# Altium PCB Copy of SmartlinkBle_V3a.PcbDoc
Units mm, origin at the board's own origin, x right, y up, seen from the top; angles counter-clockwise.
Board outline 125 x 27 mm, 6 copper layers (Top Layer, PWR, VCC, GND, Signal, Bottom Layer), stack 1.475 mm thick; 29 components, 147 nets, 142 pads, 70 vias.
Unrouted connection lines stored in the file: 5.
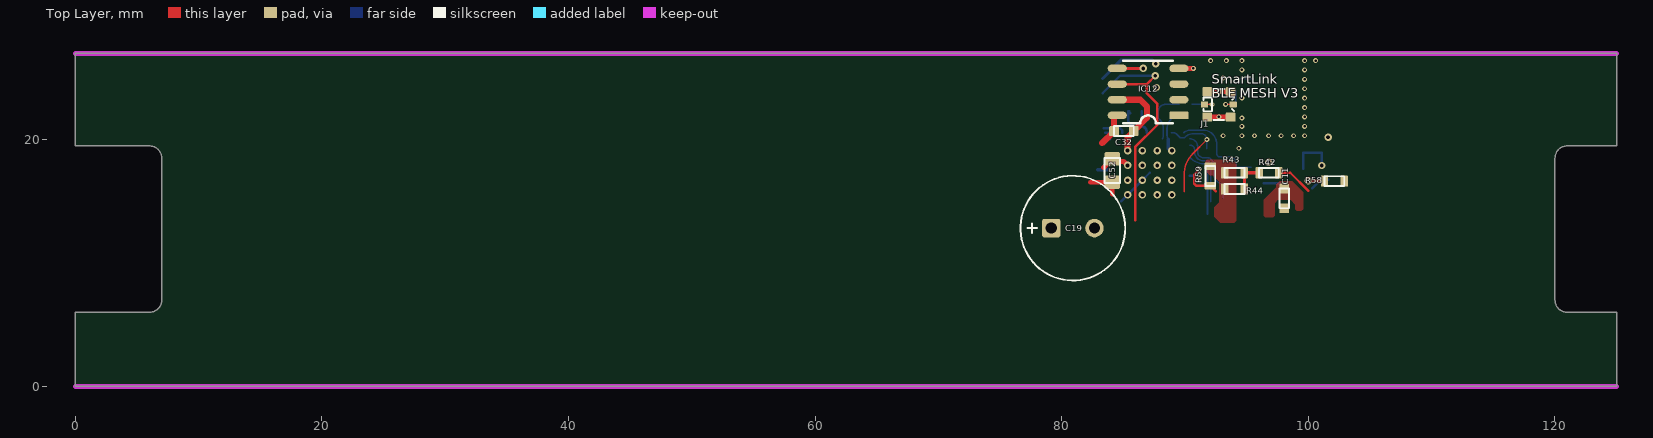
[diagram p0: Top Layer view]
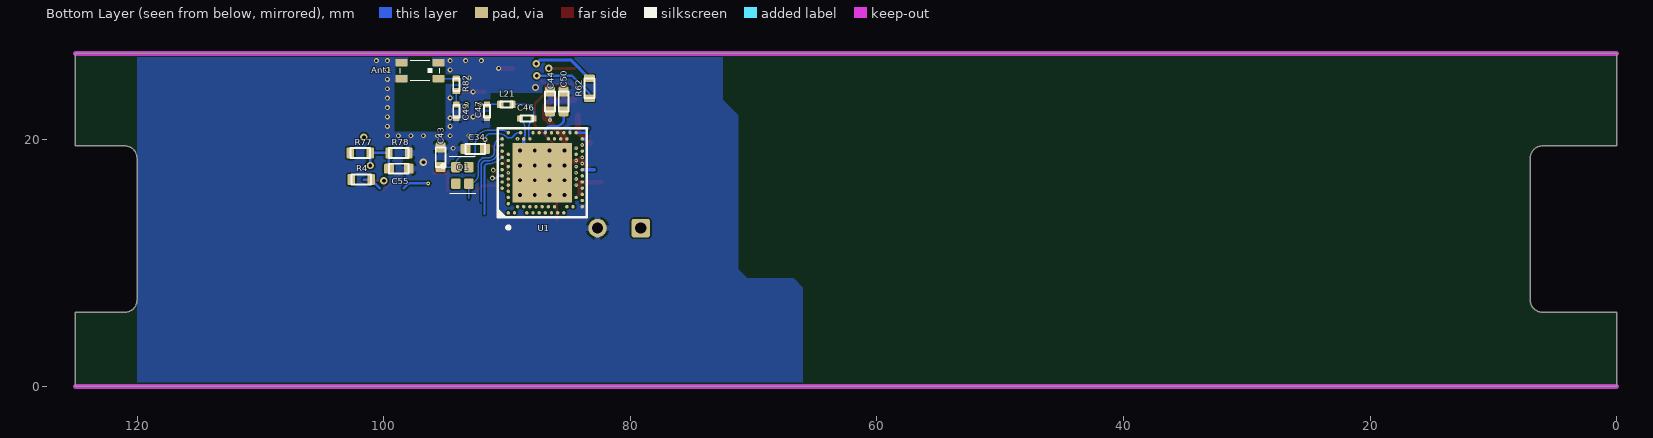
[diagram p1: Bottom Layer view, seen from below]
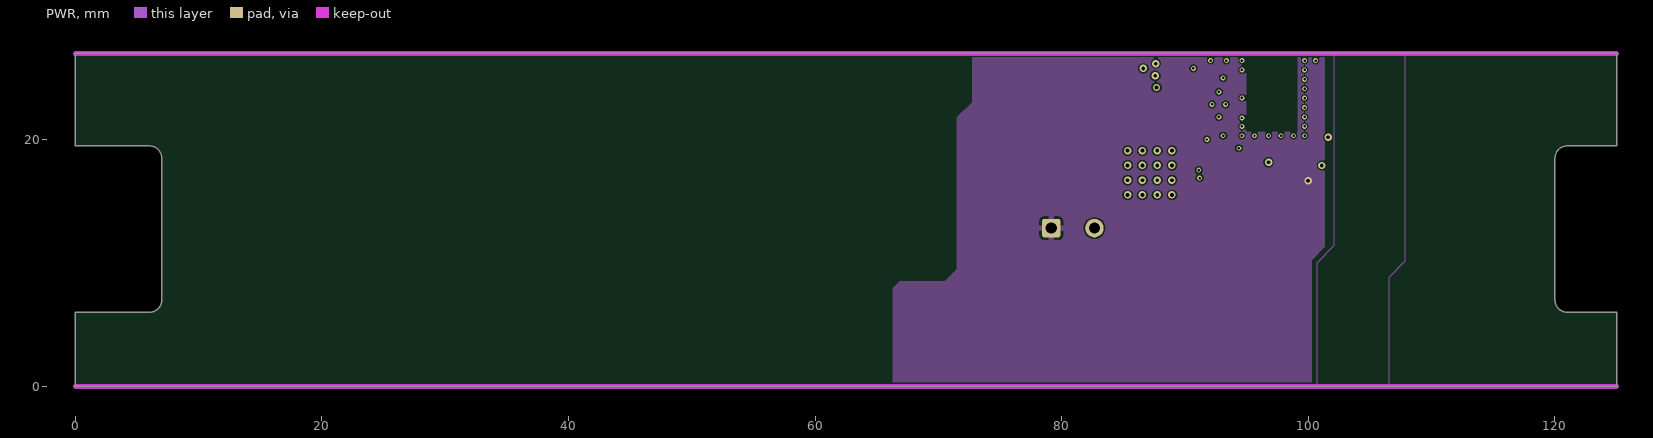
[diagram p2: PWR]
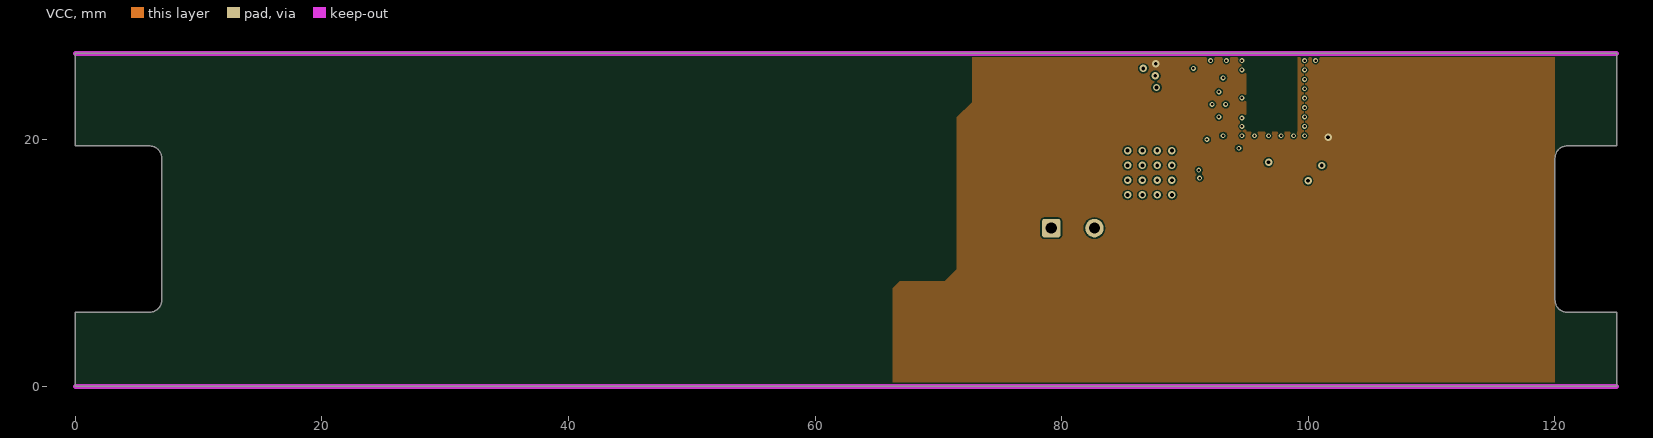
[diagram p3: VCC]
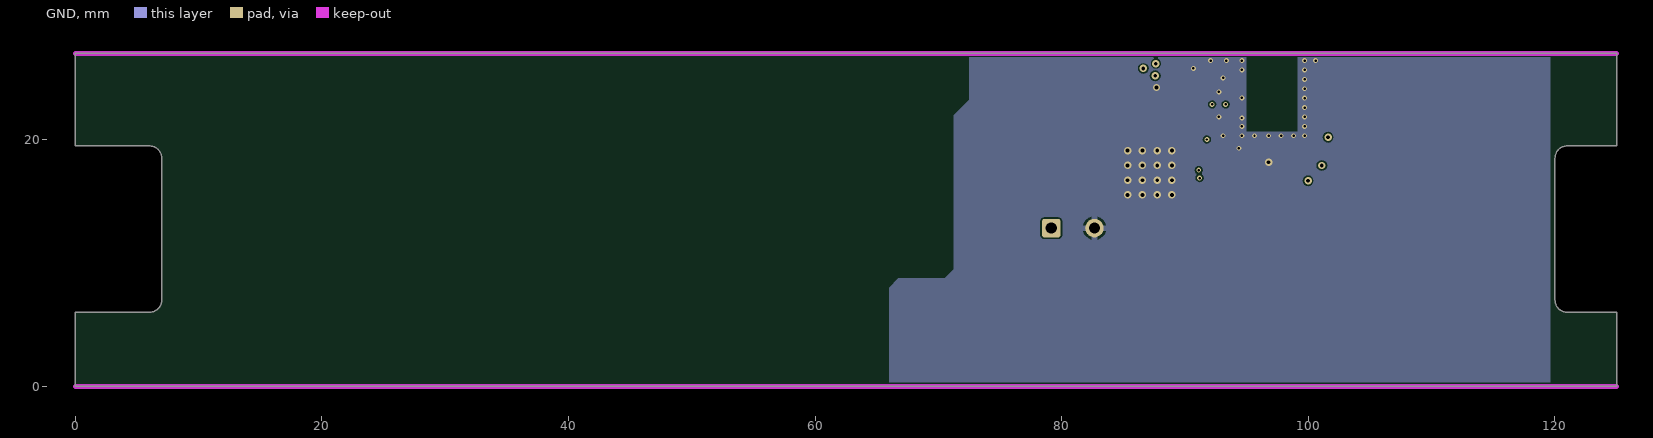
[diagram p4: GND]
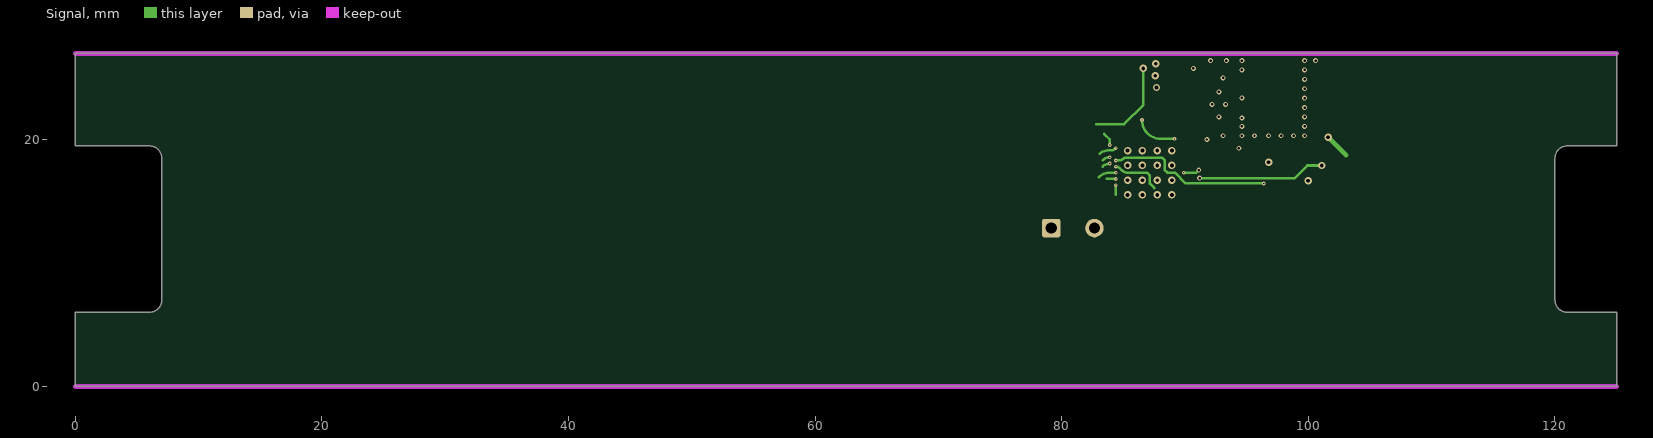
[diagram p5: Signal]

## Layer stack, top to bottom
Top Solder: solder mask 0.015, WE-SM-0001, Dk 3.5
Top Layer: signal copper 0.03
Dielectric 1: prepreg 0.065, WE-PP-0034, Dk 3.5
PWR: signal copper 0.035
Core 1: core 0.51, WE-CO-0050, Dk 5.1
VCC: signal copper 0.035
Dielectric 2: prepreg 0.125, WE-PP-0035, Dk 3.7
GND: signal copper 0.035
Core 2: core 0.51, WE-CO-0050, Dk 5.1
Signal: signal copper 0.035
Dielectric 3: prepreg 0.065, WE-PP-0034, Dk 3.5
Bottom Layer: signal copper 0.03
Bottom Solder: solder mask 0.015, WE-SM-0001, Dk 3.5

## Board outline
0,6 6,6 ccw(c6,7) 7,7 7,18.5 ccw(c6,18.5) 6,19.5 0,19.5 0,27 125,27 125,19.5 121,19.5 ccw(c121,18.5) 120,18.5 120,7 ccw(c121,7) 121,6 125,6 125,0 0,0

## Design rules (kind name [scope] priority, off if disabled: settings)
Clearance "Prim - Sec" [InNetClass('Sec LS') vs (InNetClass('AC N') OR InNetClass('AC Ph') OR InNetClass('Pri HS') OR InNetClass('Pri LS') OR InNetClass('Pri MS') OR InNetClass('Pri SW') OR InNetClass('GND-PRI'))] p1: gap=6 ignorepadtopadclearanceinfootprint=FALSE
Clearance "Bus - N" [InNet('BUS+') vs InNetClass('AC N')or InNetClass('Touch')] p2: gap=2.5 ignorepadtopadclearanceinfootprint=FALSE
Clearance Earth [InNetClass('Earth') vs (InNetClass('AC N') OR InNetClass('AC Ph') OR InNetClass('Pri HS') OR InNetClass('Pri LS') OR InNetClass('Pri MS') OR InNetClass('Pri SW') OR InNetClass('GND-PRI'))] p3: gap=2.5 ignorepadtopadclearanceinfootprint=FALSE
Clearance "AC-PH - AC-N" [InNetClass('AC Ph') vs InNetClass('AC N')] p4: gap=2.5 ignorepadtopadclearanceinfootprint=FALSE
Clearance "Touch - Netz" [InNetClass('Touch') vs (InNetClass('AC N') OR InNetClass('AC Ph') OR InNetClass('Pri HS') OR InNetClass('Pri LS') OR InNetClass('Pri MS') OR InNetClass('Pri SW') OR InNetClass('GND-PRI'))] p5: gap=1 ignorepadtopadclearanceinfootprint=FALSE
Clearance "TouchLS - Netz" [InNetClass('Touch_LS') vs (InNetClass('AC N') OR InNetClass('AC Ph') OR InNetClass('Pri HS') OR InNetClass('Pri LS') OR InNetClass('Pri MS') OR InNetClass('Pri SW') OR InNetClass('GND-PRI'))] p6: gap=0.5 ignorepadtopadclearanceinfootprint=FALSE
Clearance "Bus + to Bus -" [InNet('BUS+') vs InNet('BUS-')] p7: gap=1 ignorepadtopadclearanceinfootprint=FALSE
Clearance "earth Sec" [InNetClass('Earth') vs InNetClass('Sec LS')] p8: gap=1 ignorepadtopadclearanceinfootprint=FALSE
Clearance "AC to Pri" [(InNetClass('AC N') OR InNetClass('AC Ph')) vs (InNetClass('Pri HS') OR InNetClass('Pri LS') OR InNetClass('GND-PRI'))] p9: gap=1 ignorepadtopadclearanceinfootprint=FALSE
Clearance GND-PRI [InNetClass('GND-PRI') vs (InNetClass('AC N') OR InNetClass('AC Ph') OR InNetClass('Pri HS') OR InNetClass('Pri LS') OR InNetClass('Pri MS') OR InNetClass('Pri SW'))] p10: gap=0.99 ignorepadtopadclearanceinfootprint=FALSE
Clearance "Pri SW" [InNetClass('Pri SW')] p11: gap=1 ignorepadtopadclearanceinfootprint=FALSE
Clearance "Pri HS - Pri LS" [InNetClass('Pri HS') vs InNetClass('Pri LS')] p12: gap=1 ignorepadtopadclearanceinfootprint=FALSE
Clearance Pri-MS [InNetClass('Pri MS')] p13: gap=0.5 ignorepadtopadclearanceinfootprint=FALSE
Clearance All [All] p14: gap=0.12 ignorepadtopadclearanceinfootprint=FALSE
ComponentClearance ComponentClearance_C13 [InComponent('C13')] p1: gap=0 collisioncheckmode=3 verticalgap=0 showdistances=TRUE
ComponentClearance ComponentClearance_RTC [InComponent('RTC1')] p2: gap=0 collisioncheckmode=3 verticalgap=0 showdistances=TRUE
ComponentClearance ComponentClearance_Ref [HasFootprint('SMD-REF1')] p3: gap=0 collisioncheckmode=3 verticalgap=0 showdistances=TRUE
ComponentClearance ComponentClearance_VDR1_C14 [InComponent('VDR1') vs InComponent('C14')] p4: gap=0 collisioncheckmode=3 verticalgap=0 showdistances=TRUE
ComponentClearance ComponentClearance_ST3_ST1 [InComponent('ST1') vs InComponent('ST3')] p5: gap=0 collisioncheckmode=3 verticalgap=0 showdistances=TRUE
ComponentClearance ComponentClearance_C27_TR1 [InComponent('C27') vs InComponent('TR1')] p6: gap=0 collisioncheckmode=3 verticalgap=0 showdistances=TRUE
ComponentClearance [All] p7: gap=0.254 collisioncheckmode=3 verticalgap=0.254 showdistances=TRUE
DiffPairsRouting [InNetClass('50Ohms_Antenna')] p1: maxlimit=0.127 minlimit=0.127 mostfreqgap=0.127 toplayer_minwidth=0.089 toplayer_maxwidth=0.089 toplayer_prefwidth=0.089 midlayer1_minwidth=0.042 midlayer1_maxwidth=0.042 midlayer1_prefwidth=0.042 midlayer2_minwidth=0.042 midlayer2_maxwidth=0.042 midlayer2_prefwidth=0.042 midlayer3_minwidth=0.062 midlayer3_maxwidth=0.062 midlayer3_prefwidth=0.062 midlayer4_minwidth=0.062 midlayer4_maxwidth=0.062 midlayer4_prefwidth=0.062 bottomlayer_minwidth=0.089 bottomlayer_maxwidth=0.089 bottomlayer_prefwidth=0.089 impedanceprofiledriven=TRUE impedanceprofileid={EC742D13-3309-4660-A8FB-E4D3CA0C2C87} impedanceprofilevalue=100.000000 maxuncoupledlength=12.7
FabricationTestPointUsage TestPointUsage [All] p1: valid=0 allowmultiple=FALSE
FabricationTestpoint Testpoint [All] p1: side=3 testpointundercomponent=TRUE minsize=1.016 maxsize=2.54 preferedsize=1.524 minholesize=0 maxholesize=1.016 preferedholesize=0.813 testpointgrid=0.025 allowsidetop=TRUE allowsidebottom=TRUE usegrid=TRUE gridtolerance=0
HoleSize [All] p1: absolutevalues=TRUE maxlimit=10 minlimit=0.025 maxpercent=80.000 minpercent=20.000
MinimumSolderMaskSliver MinimumSolderMaskSliver_APDS-9250 [All vs HasFootprint('APDS-9250')] p1: minsoldermaskwidth=0.04
MinimumSolderMaskSliver [All] p2: minsoldermaskwidth=0.05
PolygonConnect BottomPolygonDirectConnect [All vs IsNamedPolygon('Bottom_DirectConnect')] p1: connectstyle=Direct reliefconductorwidth=0.254 reliefentries=4 polygonreliefangle="90 Angle" airgapwidth=0.254
PolygonConnect BottomPolygonDirectConnect_Antenna [All vs (InComponent('Ant1') AND OnBottomLayer)] p2: connectstyle=Direct reliefconductorwidth=0.254 reliefentries=4 polygonreliefangle="90 Angle" airgapwidth=0.254
PolygonConnect PolygonConnect_TopLayer [OnTopLayer] p3: connectstyle=Direct reliefconductorwidth=0.61 reliefentries=4 polygonreliefangle="90 Angle" airgapwidth=0.1
PolygonConnect IsVia [IsVia] p4: connectstyle=Direct reliefconductorwidth=0.254 reliefentries=4 polygonreliefangle="90 Angle" airgapwidth=0.254
PolygonConnect [All] p5: connectstyle=Relief reliefconductorwidth=0.5 reliefentries=4 polygonreliefangle="90 Angle" airgapwidth=0.2
RoutingVias RoutingMicroVia [IsMicroVia] p1: holewidth=0.1 width=0.3 viastyle="Through Hole" minholewidth=0.08 minwidth=0.25 maxholewidth=0.12 maxwidth=0.35
RoutingVias [All] p2: holewidth=0.3 width=0.6 viastyle="Through Hole" minholewidth=0.2 minwidth=0.4 maxholewidth=1.5 maxwidth=2
SilkToSolderMaskClearance SilkscreenOverComponentPads [IsPad] p1: minsilkscreentomaskgap=0.254 clearancetoexposedcopper=TRUE
SolderMaskExpansion [All] p1: expansion=0.102 istentingtop=FALSE
Width Width_50Ohms [InNetClass('50Ohms_Antenna')] p1: maxlimit=0.144 minlimit=0.074 preferedwidth=0.144 toplayer_minwidth=0.117 toplayer_maxwidth=0.117 toplayer_prefwidth=0.117 midlayer1_maxwidth=0.074 midlayer1_prefwidth=0.074 midlayer2_maxwidth=0.074 midlayer2_prefwidth=0.074 midlayer3_minwidth=0.144 midlayer4_minwidth=0.144 bottomlayer_minwidth=0.117 bottomlayer_maxwidth=0.117 bottomlayer_prefwidth=0.117 impedanceprofiledriven=TRUE impedanceprofileid={B90CC2CE-5B6F-4977-991D-649189DA46C0} impedanceprofilevalue=50.000000 minimp=50.000000 maximp=50.000000 favimp=50.000000
Width [All] p2: maxlimit=12.7 minlimit=0.127 preferedwidth=0.203
23 further rules are at their usual default settings.

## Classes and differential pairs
net class Touch_LS: NetC38_1
net class 50Ohms_Antenna: NetAnt1_4 NetC47_1 NetC49_1
net class Touch: NetD8_1 NetR35_1 NetR36_1 Touch1
net class Earth: Earth
net class "Pri SW": NetC17_1
net class GND-PRI: GND-PRI NetC28_1 NetIC9_2
component class SmartlinkBle_V3_P4: C11 C19 R42 R43 R44
component class SmartlinkBle_V3_P1: Ant1 C32 C34 C43 C44 C46 C47 C49 C50 C52 C55 IC12 J1 L21 Q1 R58 R59 R62 R77 R78 R82 U1
net class "AC Ph": NetC14_1 NetD10_2 P
net class "Pri LS": +24V -24V BUS+ BUS- NetC29_1 NetC29_2 NetC31_1 NetC37_2 NetD4_2 NetD4_3 NetD6_1 NetD6_2 NetD7_1 NetD13_2 NetD17_1 NetD18_2 NetD19_1 NetD19_2 NetIC10_1 NetR21_1 NetR23_1 NetR23_2 NetR25_1 NetR26_1 NetR32_2 NetR50_2 NetR54_1 NetR54_2 NetR55_1 NetR69_2
net class "Sec LS": 5V5_Feedback +3V3 +3V3_RTC +5V5 +16V "Bus EN" "Bus RX" "Bus TX" DALI1_RX DALI1_TX DALI2_PWM DALI2_RX DALI2_TX enable_3V3 enable_5V5 Ext_SCL Ext_SDA GND HWV LEDgreen LEDred NetAnt1_4 NetC2_1 NetC2_2 NetC4_1 NetC5_1 NetC6_1 NetC8_1 NetC9_1 NetC11_1 NetC11_2 NetC22_1 NetC22_2 NetC34_1 NetC44_1 NetC45_1 NetC46_1 NetC47_1 NetC49_1 NetC50_1 NetC57_1 NetD12_2 NetIC1_2 NetIC1_4 NetIC2_2 NetIC2_4 NetIC3_3 NetIC3_4 NetIC4_1 NetIC4_2 NetIC5_1 NetIC5_2 NetIC6_3 NetIC6_4 NetIC7_3 NetIC8_3 NetIC11_3 NetIC11_6 NetL1_2 NetL2_2 NetL3_2 NetL4_2 NetL5_2 NetL6_2 NetL7_2 NetL8_2 NetL15_1 NetL16_1 NetL17_1 NetLED1_2 NetLED2_2 NetQ2_1 NetQ2_3 NetQ3_1 NetQ3_3 NetQ4_1 NetQ5_1 NetQ5_3 NetR33_2 NetR67_2 Oscillator_N Oscillator_P PIR_SCL PIR_SDA R\S\T\ SCL SCL_Buffer SDA SDA_Buffer SWCLK SWDIO SWO Touch U16V VCOM_RX VCOM_TX
net class "AC N": N
net class "Pri HS": VPRI
component class SmartlinkBle_V3_P2: R4 Sc1
differential pair Oscillator: +Oscillator_P -Oscillator_N

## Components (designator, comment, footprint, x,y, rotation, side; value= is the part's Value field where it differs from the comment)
Ant1 "2450AT18D0100E" 2450AT18D0100_right 97.05,25.6 r180 bottom locked
C11 "100n" C0603 98.044,15.24 r270 top
C19 "220u/25V" CR-LS3.5D8L11.5 80.899,12.827 r0 top
C32 "100n" C0603 85.039,20.701 r0 top
C34 "1u/10V" C0603 92.57,19.253 r0 bottom
C43 "12p" C0603 95.377,18.58 r90 bottom
C44 "100p" C0603 86.5,23.1 r90 bottom
C46 "0.8p/50V" C0402 88.392,21.717 r0 bottom
C47 "0.5p/50V" C0402 91.618,22.31 r270 bottom
C49 "1.5p/50V" C0402 94.107,22.31 r270 bottom
C50 "820p" C0603 85.4,23.1 r90 bottom
C52 "10u/10V" C0805 84.1,17.5 r90 top
C55 "100n" C0603 98.768,17.653 r180 bottom
IC12 "CAT24C128" SOIC-8_small 89.5,21.971 r180 top
J1 "MM8130-2600" MM8130-2600R 92.744,22.86 r270 top
L21 "4.7nH 0402" L0402 90.043,22.86 r0 bottom
Q1 "32MHz" ECX-1637B 93.616,17.105 r270 bottom
R4 "68R" R0603 101.816,16.764 r0 bottom
R42 "33k" R0603 96.802,17.319 r0 top
R43 "82k" R0603 94.008,17.319 r0 top
R44 "12k" R0603 94.008,16.002 r0 top
R58 "10k" R0603 102.108,16.637 r180 top
R59 "1k0" R0603 92.043,17.058 r270 top
R62 "2k2" R0603 83.312,24.168 r90 bottom
R77 "10k" R0603 101.892,18.923 r0 bottom
R78 "6k8" R0603 98.768,18.923 r0 bottom
R82 "0R0" R0402 94.107,24.45 r90 bottom
Sc1 "scoring" scoring 56.356,176.371 r0 top
U1 "nRF52840" AQFN50P700X700X85_HS-74N 87.138,17.316 r90 bottom locked

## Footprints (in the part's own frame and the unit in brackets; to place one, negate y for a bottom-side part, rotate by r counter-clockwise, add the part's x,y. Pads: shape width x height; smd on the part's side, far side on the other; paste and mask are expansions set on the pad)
2450AT18D0100_right [mm] "2.4 GHz Mini Chip Antenna"
  rrect25% 1x0.6 smd: 1(1.5,0.65) 2(-1.5,0.65) 3(-1.5,-0.65) 4(1.5,-0.65)
  silkscreen extent -1.6,-0.8 1.6,0.8, body extent -1.6,-0.8 1.6,0.8, height 1.21
AQFN50P700X700X85_HS-74N [mm]
  rect 4.85x4.85 smd mask+0.05: 74(0,0)
  round 0.275 smd paste+0.012 mask+0.05: A8(-1.25,3.25) A10(-0.75,3.25) A12(-0.25,3.25) A14(0.25,3.25) A16(0.75,3.25) A18(1.25,3.25) A20(1.75,3.25) A22(2.25,3.25) A23(2.75,3.25) AA24(3.25,-2.25) AB2(-2.75,-2.5) AC5(-2,-2.75) AC9(-1,-2.75) AC11(-0.5,-2.75) AC13(0,-2.75) AC15(0.5,-2.75) AC17(1,-2.75) AC19(1.5,-2.75) AC21(2,-2.75) AC24(3.25,-2.75) AD2(-2.75,-3.25) AD4(-2.25,-3.25) AD6(-1.75,-3.25) AD8(-1.25,-3.25) AD10(-0.75,-3.25) AD12(-0.25,-3.25) AD14(0.25,-3.25) AD16(0.75,-3.25) AD18(1.25,-3.25) AD20(1.75,-3.25) AD22(2.25,-3.25) AD23(2.75,-3.25) B1(-3.25,2.75) B3(-2.5,2.75) B5(-2,2.75) B7(-1.5,2.75) B9(-1,2.75) B11(-0.5,2.75) B13(0,2.75) B15(0.5,2.75) B17(1,2.75) B19(1.5,2.75) B24(3.25,2.75) C1(-3.25,2.25) D2(-2.75,2) D23(2.75,2) E24(3.25,1.75) F2(-2.75,1.5) F23(2.75,1.5) G1(-3.25,1.25) H2(-2.75,1) H23(2.75,1) J1(-3.25,0.75) J24(3.25,0.75) K2(-2.75,0.5) L1(-3.25,0.25) L24(3.25,0.25) M2(-2.75,0) N1(-3.25,-0.25) N24(3.25,-0.25) P2(-2.75,-0.5) P23(2.75,-0.5) R1(-3.25,-0.75) R24(3.25,-0.75) T2(-2.75,-1) T23(2.75,-1) U1(-3.25,-1.25) U24(3.25,-1.25) V23(2.75,-1.5) W1(-3.25,-1.75) W24(3.25,-1.75) Y2(-2.75,-2) Y23(2.75,-2)
  silkscreen extent -4.56,-3.6 3.6,3.6, body extent -3.55,-3.55 3.55,3.55, height 0.85
C0402 [mm] "Chip Capacitor   1,0 x 0,5mm"
  rrect25% 0.5x0.5 smd: 1(-0.55,0) 2(0.55,0)
  silkscreen extent -0.5,-0.25 0.5,0.25, body extent -0.5,-0.25 0.5,0.25, height 0.5
C0603 [mm] "Chip Capacitor   1,8 x 0,8mm"
  rrect25% 0.8x0.8 smd: 1(-0.8,0) 2(0.8,0)
  silkscreen extent -0.8,-0.4 0.8,0.4, body extent -0.8,-0.4 0.8,0.4, height 0.8
C0805 [mm] "Chip Capacitor   2,0 x 1,25mm"
  rrect25% 1.1x1.25 smd: 1(-0.95,0) 2(0.95,0)
  silkscreen extent -1,-0.63 1,0.63, body extent -1,-0.63 1,0.63, height 0.85
CR-LS3.5D8L11.5 [mm] "Capacitor  radial  D=8mm  r=3.5mm H=11.5mm"
  rrect25% 1.5x1.5 hole 0.9: 1(-1.75,0)
  round 1.5 hole 0.9: 2(1.75,0)
  silkscreen extent -4.25,-4.25 4.25,4.25, body extent -3.97,-3.99 4,3.99, height 11.5
ECX-1637B [mm] "Quarz ECS 2x1.6mm"
  rrect25% 0.85x0.75 smd: 1(-0.675,-0.525) 2(0.675,-0.525) 3(0.675,0.525) 4(-0.675,0.525)
  silkscreen extent -1.5,-1.68 1.5,1.07, body extent -1,-0.8 1,0.8, height 0.55
L0402 [mm] "Chip Inductors 1.0 x 0.5mm"
  rrect25% 0.5x0.6 smd: 1(-0.5,0) 2(0.5,0)
  silkscreen extent -0.5,-0.25 0.5,0.25, body extent -0.5,-0.25 0.5,0.25, height 0.5
MM8130-2600R [mm]
  rrect25% 0.5x0.58 smd: 1(0,1.16) 3(0,-1.16)
  rrect25% 0.75x0.8 smd: 2(-1.025,0.95) 2(-1.025,-0.95) 2(1.025,0.95) 2(1.025,-0.95)
  Top Layer pour cut-out: 0.65,-0.55 -0.65,-0.55 -0.65,-1.35 0.65,-1.35
  Top Layer pour cut-out: -0.65,0.55 0.65,0.55 0.65,1.35 -0.65,1.35
  silkscreen extent -1.25,-1.25 1.25,1.25, body extent -1.26,-1.3 1.26,1.3, height 1.4
R0402 [mm] "Chip Resistor 1.0 x 0.5mm"
  rrect25% 0.5x0.6 smd: 1(-0.5,0) 2(0.5,0)
  silkscreen extent -0.5,-0.25 0.5,0.25, body extent -0.5,-0.25 0.5,0.25, height 0.35
R0603 [mm] "Chip Resistor 1.6x 0.8mm"
  rrect25% 0.6x0.9 smd: 1(-0.8,0) 2(0.8,0)
  silkscreen extent -0.8,-0.4 0.8,0.4, body extent -0.8,-0.4 0.8,0.4, height 0.45
scoring [mm]
SOIC-8_small [mm]
  rrect25% 1.55x0.6 smd: 1(0,0)
  oval 1.55x0.6 smd: 2(0,-1.27) 3(0,-2.54) 4(0,-3.81) 5(5,-3.81) 6(5,-2.54) 7(5,-1.27) 8(5,0)
  silkscreen extent 0.5,-4.44 4.5,0.64, body extent -0.5,-4.35 5.28,0.55, height 1.45

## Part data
Ant1: library part "ChipAntenna 2.4GHz 2450AT18D0100 Antenna fed right", "2.45 GHz SMD Antenna, EIA 1206, Detuning resilient, / Edge Mount Design"
C11 C32 C55: library part "100n/50V 0603", "100nF 50V ±10%  X7R"
C19: library part EL-220u/25V, "Nichicon 220uF/25V Iac=550mA"
C34: library part "1u/10V 0603", "1uF 10V ±10%   X7R"
C43: library part "12p/50V 0603", "12pF 50V ±5%   COG"
C44: library part "100p/50V 0603", "100pF 50V ±5%   COG"
C46: library part "0.8p/50V 0402 C0G", "0.8pF 50V ±0.1pF C0G (NP0) SMT 0402"
C47: library part "0.5p/50V 0402 C0G", "0.5pF 50V ±0.1pF C0G (NP0) SMT 0402"
C49: library part "1.5p/50V 0402 C0G", "1.5pF 50V ±0.1pF C0G (NP0) SMT 0402"
C50: library part "820p/50V 0603 COG", "820pF 50V ±5% COG"
C52: library part "10u/10V 0805", "10µF 10V ±10%  X7R"
IC12: "128k I2C Serial EEPROM 8x16k"
J1: "Coaxial Connector with Switch MM8130-2600"
L21: library part "LQW15AN4N7B00D 4.7nH 0402", "RF Inductor Muarata LQW15AN4N7B00D 4.7nH ± 0.1nH 750mA 70mOhm"
Q1: library part Quarz-ECX-1637B-32MHz, "ECS Quarz  32MHz±10ppm  ESR=50R"
R4: library part "68R 0603", "68R     100mW   0603   1%   max 50V"
R42: library part "33k 0603", "33k     100mW   0603   1%   max 50V"
R43: library part "82k 0603", "82k      100mW   0603   1%   max 50V"
R44: library part "12k 0603", "12k     100mW   0603   1%   max 50V"
R58 R77: library part "10k 0603", "10k     100mW   0603   1%   max 50V"
R59: library part "1k0 0603", "1k0      100mW   0603   1%   max 50V"
R62: library part "2k2 0603", "2k2      100mW   0603   1%   max 50V"
R78: library part "6k8 0603", "6k8      100mW   0603   1%   max 50V"
R82: library part "0R0 0402", "Imax = 2A"
U1: "Multi-protocol Bluetooth Low Energy, IEEE 802.15.4, ANT and 2.4GHz proprietary system-on-chip"

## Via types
v1: diameter 0.4, hole 0.2, Top Layer to Bottom Layer, tented both sides, 33 vias
v2: diameter 0.61, hole 0.305, Top Layer to Bottom Layer, 16 vias
v3: diameter 0.3, hole 0.1, Signal to Bottom Layer, tented both sides, 13 vias
v4: diameter 0.6, hole 0.3, Top Layer to Bottom Layer, tented both sides, 8 vias

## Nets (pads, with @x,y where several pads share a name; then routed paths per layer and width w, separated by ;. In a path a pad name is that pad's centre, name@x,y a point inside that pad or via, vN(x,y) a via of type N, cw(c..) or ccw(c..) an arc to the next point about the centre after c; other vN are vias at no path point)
5V5_Feedback: C55.1 R77.1 R78.2 U1.A12 | length 15
  Signal w0.203: v1(91.186,16.891) 98.908,16.891 99.924,17.907 v4(101.092,17.907)
  Bottom Layer w0.203: U1.A12 90.681,17.066 90.856,16.891 v1(91.186,16.891) ; C55.1 R78.2 R77.1 v4(101.092,17.907)
+3V3: C32.1 C52.1 IC12.8 R42.2 R62.2 U1.A22 U1.AD14 U1.AD23 U1.B1 U1.W1 U1.Y2 | length 22.5
  Top Layer w0.203: R42.2 98.531,17.319 99.974,15.875
  Top Layer w0.381: 82.32,16.55 C52.1 84.1,15.571
  Top Layer w0.508: 83.261,19.723 C32.1 IC12.8@84.239,21.971
  Signal w0.381: v4(101.6,20.2) 103.055,18.745
  Bottom Layer w0.127: U1.A22 cw(c90.388,19.184) 90.768,19.227 90.768,19.013 ccw(c91.494,19.013) 91.494,18.287 91.761,18.287 cw(c91.761,17.973) 92.075,17.973 92.075,14.986
  Bottom Layer w0.254: 82.898,17.566 U1.AD14 ; R62.2 84.819,26.475 87.317,26.475 v4(87.63,26.162) ; 83.573,20.066 U1.AD23
+3V3_RTC: 
+5V5: R77.2
+16V: C19.1 R58.2 | length 1.3
  Top Layer w0.203: v4(99.974,16.662) 101.283,16.662 R58.2
+24V: 
-24V: 
"Bus EN": U1.AC21 | length 1.4
  Signal w0.203: 83.068,18.857 cw(c83.718,18.206) 83.718,19.126 83.93,19.126 ccw(c83.93,19.774) v3(84.388,19.316)
"Bus RX": U1.P2
"Bus TX": U1.AC9 | length 0.8
  Signal w0.203: 84.388,15.554 v3(84.388,16.316)
BUS+: 
BUS-: 
DALI1_RX: U1.N1
DALI1_TX: U1.M2
DALI2_PWM: U1.K2
DALI2_RX: U1.R1
DALI2_TX: U1.T2
Earth: 
enable_3V3: U1.J1
enable_5V5: U1.L1
Ext_SCL: U1.AC15 | length 4.2
  Signal w0.203: v3(84.388,17.816) cw(c84.388,17.373) 84.701,17.686 84.831,17.556 ccw(c85.395,18.12) 85.395,17.323 86.919,17.323 87.147,17.094 87.147,16.434 87.506,16.075
Ext_SDA: R4.1 U1.AC17 | length 17.2
  Signal w0.203: v3(84.388,18.316) 84.627,18.316 ccw(c84.627,18.827) 84.988,18.466 cw(c85.172,18.282) 85.172,18.542 88.138,18.542 88.341,18.339 88.341,17.551 88.57,17.323 89.179,17.323 90.05,16.452 96.373,16.452 v3(96.375,16.45)
  Bottom Layer w0.203: v3(96.375,16.45) 97.977,16.45 98.374,16.053 ; 100.305,16.053 R4.1 101.625,16.764
GND: Ant1.1 Ant1.2 Ant1.3 C19.2 C32.2 C34.2 C43.2 C44.2 C46.2 C47.2 C49.2 C50.2 C52.2 C55.2 IC12.4 IC12.7 J1.2 R43.1 R44.1 R59.1 R78.1 U1.74 U1.AD2 U1.B7 U1.F23 | length 20.2
  Top Layer w0.381: IC12.4 v1(90.678,25.781) ; J1.2@91.794,21.835 91.803,21.844 v1(92.744,21.844) 93.685,21.844 J1.2@93.694,21.835 ; J1.2@91.794,23.885 91.803,23.876 v1(92.744,23.876) 93.685,23.876 J1.2@93.694,23.885
  Top Layer w0.4: 83.379,17.729 C52.2 84.314,18.236 85.018,18.236 v2(85.338,17.916)
  Top Layer w0.5: IC12.7 86.359,23.241 86.9,22.7 86.9,21.762 C32.2 85.338,20.2 v2(85.338,19.116)
  Bottom Layer w0.127: U1.F23 cw(c88.883,20.311) 88.536,20.311 88.536,20.944 cw(c89.442,20.944) 88.802,21.585 C46.2@88.934,21.717
  Bottom Layer w0.203: U1.74@84.819,14.997 v2(86.538,16.716) U1.74
  Bottom Layer w0.254: U1.74@88.638,19.253 U1.F23
  other v1: 94.361,19.304 93.091,20.32 94.615,20.32 95.631,20.32 96.774,20.32 97.79,20.32 98.806,20.32 99.695,20.32 94.615,21.082 99.695,21.082 94.615,21.76 99.695,21.844 99.695,22.606 94.615,23.385 99.695,23.368 99.695,24.13 99.695,24.892 93.091,25.019 94.615,25.654 99.695,25.654 92.075,26.416 93.345,26.416 94.615,26.416 99.695,26.416 100.584,26.416
  other v2: 85.338,15.516 86.538,15.516 87.738,15.516 88.938,15.516 85.338,16.716 87.738,16.716 88.938,16.716 86.538,17.916 87.738,17.916 88.938,17.916 86.538,19.116 87.738,19.116 88.938,19.116
  other v4: 96.774,18.161 87.681,24.232
GND-PRI: 
HWV: R59.2 U1.B13 | length 4.5
  Top Layer w0.203: v1(91.11,17.526) 90.738,17.154 90.738,16.452 90.933,16.258 R59.2 92.469,15.832
  Signal w0.203: v3(89.888,17.316) 90.9,17.316 v1(91.11,17.526)
LEDgreen: U1.U1
LEDred: U1.AC11 | length 0.7
  Signal w0.203: 83.643,16.816 v3(84.388,16.816)
N: 
NetAnt1_4: Ant1.4 R82.2 | length 1.4
  Bottom Layer w0.117: R82.2 Ant1.4
NetC2_1: 
NetC2_2: 
NetC4_1: R4.2
NetC5_1: 
NetC6_1: 
NetC8_1: 
NetC9_1: 
NetC11_1: C11.1
NetC11_2: C11.2
NetC14_1: 
NetC16_2: 
NetC17_1: 
NetC17_2: 
NetC22_1: 
NetC22_2: 
NetC28_1: 
NetC29_1: 
NetC29_2: 
NetC31_1: 
NetC34_1: C34.1 U1.B5 U1.E24 | length 9
  Top Layer w0.127: 89.917,15.787 89.917,17.11 cw(c92.457,17.11) 90.661,18.906 v1(91.77,20.015)
  Bottom Layer w0.127: U1.E24 89.055,20.566 cw(c89.055,20.246) 89.281,20.472 89.521,20.232 ccw(c89.738,20.449) 89.738,20.142 89.834,20.142 ccw(c89.834,20.402) 90.018,20.218 cw(c90.692,19.544) 90.692,20.498 91.288,20.498 cw(c91.288,20.015) v1(91.77,20.015) C34.1
NetC37_2: 
NetC38_1: 
NetC44_1: C44.1 U1.D23 | length 4.2
  Signal w0.203: v3(86.5,21.59) ccw(c88.024,21.59) 88.024,20.066 v3(89.138,20.066)
  Bottom Layer w0.203: v3(86.5,21.59) C44.1
NetC45_1: U1.C1
NetC46_1: C46.1 L21.1 U1.H23 | length 4.4
  Bottom Layer w0.127: C46.1 87.842,22.31 cw(c88.392,22.31) 88.392,22.86 L21.1 ; C46.1@87.85,21.717 C46.1@87.982,21.585 ; C46.1@87.974,21.585 cw(c87.334,20.944) 88.24,20.944 88.24,20.311 cw(c87.893,20.311) U1.H23
NetC47_1: C47.1 J1.3 L21.2 | length 2.3
  Top Layer w0.117: J1.3 v1(92.194,22.86)
  Bottom Layer w0.117: L21.2 C47.1 v1(92.194,22.86)
NetC49_1: C49.1 J1.1 R82.1 | length 2.5
  Top Layer w0.117: v1(93.294,22.86) J1.1
  Bottom Layer w0.117: v1(93.294,22.86) C49.1 R82.1
NetC50_1: C50.1 U1.N24 | length 3
  Bottom Layer w0.203: C50.1 85.4,21.568 ccw(c85.743,21.568) 85.5,21.326 ccw(c86.104,21.93) 86.104,21.076 86.462,21.076 cw(c86.462,20.65) 86.888,20.65 U1.N24 ; C50.1@85.471,22.3 ccw(c85.713,22.3) C50.1@85.542,22.129
NetC57_1: U1.A18 | length 5.5
  Bottom Layer w0.127: U1.A18 90.462,18.491 ccw(c91.567,19.596) 91.567,18.034 cw(c91.567,17.78) 91.821,17.78 91.821,13.97
NetD4_2: 
NetD4_3: 
NetD6_1: 
NetD6_2: 
NetD7_1: 
NetD8_1: 
NetD10_2: 
NetD12_2: 
NetD13_2: 
NetD16_1: 
NetD17_1: 
NetD18_2: 
NetD19_1: 
NetD19_2: 
NetIC1_2: 
NetIC1_4: 
NetIC2_2: 
NetIC2_4: 
NetIC3_3: 
NetIC3_4: 
NetIC4_1: 
NetIC4_2: 
NetIC5_1: 
NetIC5_2: 
NetIC6_3: 
NetIC6_4: 
NetIC7_3: R42.1 R43.2 R44.2 | length 2.6
  Top Layer w0.254: R44.2@94.808,15.865 R43.2 R42.1
NetIC8_3: 
NetIC9_2: 
NetIC10_1: 
NetIC11_3: 
NetIC11_6: 
NetL1_2: 
NetL2_2: 
NetL3_2: 
NetL4_2: 
NetL5_2: 
NetL6_2: 
NetL7_2: 
NetL8_2: 
NetL15_1: 
NetL16_1: 
NetL17_1: 
NetLED1_2: 
NetLED2_2: 
NetQ2_1: 
NetQ2_3: 
NetQ3_1: 
NetQ3_3: 
NetQ4_1: 
NetQ5_1: 
NetQ5_3: 
NetR21_1: 
NetR23_1: 
NetR23_2: 
NetR25_1: 
NetR26_1: 
NetR32_2: 
NetR33_2: 
NetR35_1: 
NetR36_1: 
NetR39_2: 
NetR40_1: 
NetR50_2: 
NetR52_1: 
NetR54_1: 
NetR54_2: 
NetR55_1: 
NetR67_2: 
NetR69_2: 
Oscillator_N: C43.1 Q1.1 U1.B24 | length 7.7
  Bottom Layer w0.127: U1.B24 cw(c90.398,20.056) 90.398,20.777 90.638,20.777 91.446,20.777 cw(c91.446,19.653) 92.456,20.147 cw(c91.446,19.653) 92.545,19.89 cw(c91.446,19.653) 92.57,19.653 92.57,18.853 ccw(c92.818,18.853) 92.818,18.605 93.616,18.605 cw(c93.616,18.08) 94.141,18.08 Q1.1 C43.1
Oscillator_P: Q1.3 U1.A23 | length 6.5
  Bottom Layer w0.127: U1.A23 cw(c90.388,19.439) 91.015,19.439 91.015,19.013 ccw(c91.493,19.013) 91.015,18.994 ccw(c91.493,19.013) 91.402,18.544 91.76,18.544 cw(c91.76,17.974) 92.329,17.974 92.329,17.192 ccw(c93.091,17.192) Q1.3 93.091,15.24
P: 
PIR_SCL: 
PIR_SDA: 
R\S\T\: U1.AC13 | length 1.5
  Signal w0.203: 82.982,16.942 cw(c83.885,16.038) 83.885,17.316 v3(84.388,17.316)
SCL: IC12.6 R62.1 U1.H2 | length 20.4
  Top Layer w0.203: IC12.6 86.906,24.511 ; 85.954,13.462 85.954,19.406 87.757,21.209 87.757,22.911 86.906,23.762 86.906,24.511 ; v4(87.579,25.184) 86.906,24.511
  Bottom Layer w0.203: 83.312,23.768 84.728,25.184 v4(87.579,25.184)
SCL_Buffer: 
SDA: IC12.5 U1.G1 | length 9.5
  Top Layer w0.254: IC12.5 v4(86.614,25.781)
  Signal w0.203: 82.8,21.266 85.059,21.266 86.614,22.821 v4(86.614,25.781)
SDA_Buffer: 
SWCLK: U1.AA24 | length 1.8
  Bottom Layer w0.203: 83.388,20.93 84.734,20.93 84.888,20.776 U1.AA24
SWDIO: U1.AC24 | length 0.9
  Bottom Layer w0.203: 83.533,20.566 U1.AC24
SWO: U1.AD22 | length 1.1
  Signal w0.203: 83.435,20.468 83.888,20.015 v3(83.888,19.566)
Touch: U1.AD8
Touch1: 
U16V: R58.1 U1.A8
VCOM_RX: U1.AD18 | length 0.6
  Signal w0.203: 83.336,18.337 cw(c83.888,17.785) v3(83.888,18.566)
VCOM_TX: U1.AD16 | length 0.6
  Signal w0.203: 83.306,17.825 cw(c83.888,17.243) v3(83.888,18.066)
VPRI: 
pads on no net: IC12.1 IC12.2 IC12.3 Q1.2 Q1.4 U1.A10 U1.A14 U1.A16 U1.A20 U1.AB2 U1.AC5 U1.AC19 U1.AD4 U1.AD6 U1.AD10 U1.AD12 U1.AD20 U1.B3 U1.B9 U1.B11 U1.B15 U1.B17 U1.B19 U1.D2 U1.F2 U1.J24 U1.L24 U1.P23 U1.R24 U1.T23 U1.U24 U1.V23 U1.W24 U1.Y23

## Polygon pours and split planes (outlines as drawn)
+16V on PWR "Bottom Layer-No Net" (solid, remove dead copper, pour order 104): 72.752,27.001 72.752,23.052 71.5,21.8 71.5,9.5 70.5,8.5 66.856,8.5 66.3,7.944 66.3,0 100.254,0 100.254,10.211 101.346,11.303 101.346,27.1 85.4,27.1
+5V5 on PWR "+5V5_L02_P093" (solid, remove dead copper, pour order 93): 106.5,8.8 106.5,0 100.711,0 100.711,10.033 102.108,11.43 102.108,27 107.823,27 107.823,10.123
GND on Top Layer "NONET_L-01_P-001" (solid, remove dead copper, pour order 117): 93.752,18.383 91.763,18.383 91.668,18.288 91.668,17.425 91.992,17.101 92.246,17.101 92.775,16.572 92.775,14.925 92.368,14.518 92.368,13.747 92.84,13.275 93.998,13.275 94.141,13.418 94.141,17.994
NetC11_1 on Top Layer "NONET_L-01_P-001" (solid, pour order 111): 99.441,14.224 99.068,14.224 98.933,14.359 98.933,14.732 98.552,15.113 97.536,15.113 97.282,14.859 97.282,13.843 97.155,13.716 96.52,13.716 96.393,13.843 96.393,15.113 97.409,16.129 97.409,16.383 97.663,16.637 98.679,16.637 99.576,15.74 99.576,14.359
GND on GND "Bottom Layer-No Net" (solid, remove dead copper, pour order 103): 72.5,27.1 72.5,23.25 71.25,22 71.25,9.5 70.5,8.75 66.75,8.75 66,8 66,0 119.634,0 119.634,27.1
+3V3 on VCC "Bottom Layer-No Net" (solid, remove dead copper, pour order 102): 72.75,26.9 72.75,23.05 71.5,21.8 71.5,9.5 70.5,8.5 66.856,8.5 66.3,7.944 66.3,0 120,0 120,26.9
GND on Bottom Layer "Bottom Layer-GND" (solid, remove dead copper, pour order 115): 72.5,27 72.5,23.25 71.25,22 71.25,9.5 70.5,8.75 66.75,8.75 66,8 66,0 120,0 120,27

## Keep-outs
Keep-Out Layer:
  lines w0.4: 0,0 125,0 ; 0,27 125,27

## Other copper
Top Layer:
  pour cut-out: 94.95,27 94.95,20.65 99.15,20.65 99.15,27
PWR:
  pour cut-out: 94.95,27 94.95,20.65 99.15,20.65 99.15,27
Signal:
  pour cut-out: 94.95,27 94.95,20.65 99.15,20.65 99.15,27
VCC:
  pour cut-out: 94.95,27 94.95,20.65 99.15,20.65 99.15,27
GND:
  pour cut-out: 94.95,27 94.95,20.65 99.15,20.65 99.15,27
Bottom Layer:
  pour cut-out: 93.683,24.511 94.95,24.511 94.95,20.65 99.15,20.65 99.15,24.65 98.05,24.65 98.05,25.25 99.05,25.25 99.05,25.95 98.05,25.95 98.05,27 96.05,27 96.05,25.95 94.95,25.95 94.95,25.323 93.683,25.323
  pour cut-out: 91.317,20.566 91.317,23.749 86.888,23.749 86.888,20.566

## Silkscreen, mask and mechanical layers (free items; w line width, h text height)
Top Overlay:
  text "SmartLink  / BLE MESH V3" at 92.174,23.41 h0.76
Board Shape:
  lines w0.254: 0,0 125,0 ; 0,27 125,27
Mechanical 15:
  circle w0.1: c97.05,24.15 r0.1
Drawing:
  lines w0.254: -2.6,147.549 -2.6,141.6 0.002,138.998 ; -1,36 -1,47.5 cw(c0,47.5) 0,48.5 ; 0,27 125,27 ; 0,29 125,29 125,35 ; 7,36 7,47.5 ccw(c6,47.5) 6,48.5 0,48.5 ; 122.4,147.549 122.4,141.6 125.002,138.998 ; 0,48.5 0,56 ; 0,56 cw(c0,57) 0,58 ; 0,56 125,56 ; 0,58 0,64 ; 0,58 125,58 ; 0,64 cw(c0,65) -1,65 -1,76.5 cw(c0,76.5) 0,77.5 ; 0,64 6,64 ccw(c6,65) 7,65 7,76.5 ccw(c6,76.5) 6,77.5 0,77.5 ; 0,77.5 0,85 ; 0,85 cw(c0,86) 0,87 ; 0,85 125,85 ; 0,87 0,93 ; 0,87 125,87 ; 0,93 cw(c0,94) -1,94 -1,105.5 cw(c0,105.5) 0,106.5 ; 0,93 6,93 ccw(c6,94) 7,94 7,105.5 ccw(c6,105.5) 6,106.5 0,106.5 ; 0,106.5 0,114 ; 0,114 cw(c0,115) 0,116 ; 0,114 125,114 ; 0,116 0,122 ; 0,116 125,116 ; 0,122 cw(c0,123) -1,123 -1,134.5 cw(c0,134.5) 0,135.5 ; 0,122 6,122 ccw(c6,123) 7,123 7,134.5 ccw(c6,134.5) 6,135.5 0,135.5 ; 0,135.5 0,143 ; 0,143 125,143 ; 0,143 -10,143 -10,0 0,0 125,0 135,0 135,143 125,143 ; 125,35 ccw(c125,36) 126,36 126,47.5 ccw(c125,47.5) 125,48.5 ; 125,35 121,35 cw(c121,36) 120,36 120,47.5 cw(c121,47.5) 121,48.5 125,48.5 ; 125,48.5 125,56 ; 125,56 ccw(c125,57) 125,58 ; 125,58 125,64 ; 125,64 ccw(c125,65) 126,65 126,76.5 ccw(c125,76.5) 125,77.5 ; 125,64 121,64 cw(c121,65) 120,65 120,76.5 cw(c121,76.5) 121,77.5 125,77.5 ; 125,77.5 125,85 ; 125,85 ccw(c125,86) 125,87 ; 125,87 125,93 ; 125,93 ccw(c125,94) 126,94 126,105.5 ccw(c125,105.5) 125,106.5 ; 125,93 121,93 cw(c121,94) 120,94 120,105.5 cw(c121,105.5) 121,106.5 125,106.5 ; 125,106.5 125,114 ; 125,114 ccw(c125,115) 125,116 ; 125,116 125,122 ; 125,122 ccw(c125,123) 126,123 126,134.5 ccw(c125,134.5) 125,135.5 ; 125,122 121,122 cw(c121,123) 120,123 120,134.5 cw(c121,134.5) 121,135.5 125,135.5 ; 125,135.5 125,143
  text "Scoring" at -2.013,148.26 h0.64 r90
  text "Scoring" at 122.987,148.26 h0.64 r90

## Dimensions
125,0 to 125,27 on Drawing
0,0 to 125,0 on Drawing
-10,143 to 135,143 on Drawing
125,143 to 135,143 on Drawing
125,143 to 125,0 on Drawing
